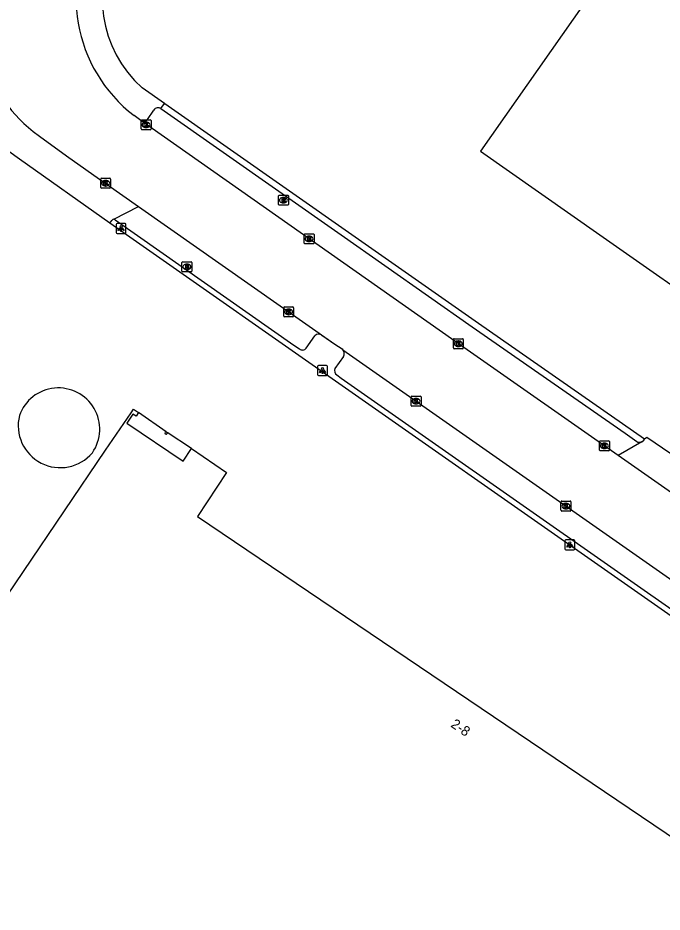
# Model space of a CAD drawing. Extents: x 155018 to 156648, y 383980 to 385733.
# Drawn here: x 155091.9 to 155156.9, y 384931.8 to 385021.9 of the extents above; entities that cross this region are included whole.
import ezdxf

# ---------------------------------------------------------------- set-up
doc = ezdxf.new("R2010")
doc.units = 0
for name, color, linetype in [('IMGEO_Brandkraan', 7, 'Continuous'), ('IMGEO_Kolk', 7, 'Continuous'), ('IMGEO_Lichtpunt', 7, 'Continuous'), ('IMGEO_Opslagtank', 7, 'Continuous'), ('IMGEO_Pand', 7, 'Continuous'), ('IMGEO_Pand_nummerreeks', 7, 'Continuous'), ('IMGEO_Pand_overbouw', 7, 'Continuous'), ('IMGEO_Rijbaan_lokaal_gesloten', 7, 'Continuous'), ('IMGEO_Rijbaan_lokaal_open', 7, 'Continuous'), ('IMGEO_Rioolput', 7, 'Continuous'), ('IMGEO_Voetpad_open', 7, 'Continuous')]:
    doc.layers.add(name, color=color, linetype=linetype)

msp = doc.modelspace()

# ---------------------------------------------------------------- linework, layer by layer
at = {"layer": 'IMGEO_Brandkraan'}
for p, q in [((155108.472, 384996.358), (155108.472, 384997.21)), ((155108.547, 384997.284), (155109.399, 384997.284)), ((155108.96, 384997.064), (155108.985, 384997.064)), ((155109.473, 384997.21), (155109.473, 384996.358)), ((155109.399, 384996.284), (155108.547, 384996.284)), ((155108.983, 384996.504), (155108.958, 384996.504))]:
    msp.add_line(p, q, dxfattribs=at)
for points in [[(155108.472, 384996.358), (155108.472, 384997.21)], [(155108.547, 384997.284), (155109.399, 384997.284)], [(155109.473, 384997.21), (155109.473, 384996.358)], [(155109.399, 384996.284), (155108.547, 384996.284)], [(155108.82, 384996.984), (155108.82, 384996.584), (155109.033, 384996.584)], [(155109.051, 384996.984), (155108.82, 384996.984)], [(155108.999, 384996.903), (155108.945, 384996.903), (155108.945, 384996.827)], [(155108.945, 384996.827), (155108.998, 384996.827)], [(155109.007, 384996.751), (155108.945, 384996.751), (155108.945, 384996.67)], [(155108.945, 384996.67), (155109.007, 384996.67)]]:
    msp.add_lwpolyline(points, dxfattribs=at)
for centre, radius, start, end in [((155108.549, 384997.208), 0.0765, 91.55205, 178.44795), ((155108.549, 384997.208), 0.0765, 91.55205, 178.44795), ((155109.397, 384997.208), 0.0765, 1.55205, 88.44795), ((155109.397, 384997.208), 0.0765, 1.55205, 88.44795), ((155108.549, 384996.36), 0.0765, 181.55205, 268.44795), ((155108.549, 384996.36), 0.0765, 181.55205, 268.44795), ((155109, 384996.865), 0.0379, 267.82845, 90.93552), ((155109.008, 384996.71), 0.0404, 269.87594, 90.50774), ((155109.039, 384996.835), 0.251, 268.66757, 293.53466), ((155109.055, 384996.839), 0.145, 59.4692, 91.53667), ((155109.08, 384996.886), 0.0922, 285.51372, 58.15012), ((155109.085, 384996.694), 0.105, 301.31148, 78.98903), ((155109.397, 384996.36), 0.0765, 271.55205, 358.44795), ((155109.397, 384996.36), 0.0765, 271.55205, 358.44795)]:
    msp.add_arc(centre, radius, start, end, dxfattribs=at)
for centre, major_axis, ratio, start_param, end_param in [((155108.959, 384996.784), (-0.387, 0.002), 0.722429, 4.712389, 7.853982), ((155108.984, 384996.784), (-0.39, 0.002), 0.717154, 1.570796, 4.712389)]:
    msp.add_ellipse(centre, major_axis=major_axis, ratio=ratio, start_param=start_param, end_param=end_param, dxfattribs=at)
at = {"layer": 'IMGEO_Kolk'}
for p, q in [((155104.355, 385010.674), (155104.355, 385011.526)), ((155104.43, 385011.6), (155105.282, 385011.6)), ((155105.356, 385011.526), (155105.356, 385010.674)), ((155105.282, 385010.6), (155104.43, 385010.6)), ((155104.866, 385010.82), (155104.841, 385010.82)), ((155104.843, 385011.38), (155104.868, 385011.38)), ((155100.283, 385004.78), (155100.283, 385005.632)), ((155100.358, 385005.706), (155101.21, 385005.706)), ((155100.771, 385005.486), (155100.796, 385005.486)), ((155101.284, 385005.632), (155101.284, 385004.78)), ((155101.21, 385004.706), (155100.358, 385004.706)), ((155100.794, 385004.926), (155100.769, 385004.926)), ((155120.785, 384999.18), (155120.785, 385000.032)), ((155120.86, 385000.106), (155121.712, 385000.106)), ((155121.273, 384999.886), (155121.298, 384999.886)), ((155121.786, 385000.032), (155121.786, 384999.18)), ((155121.712, 384999.106), (155120.86, 384999.106)), ((155121.296, 384999.326), (155121.271, 384999.326)), ((155118.723, 384991.815), (155118.723, 384992.667)), ((155118.798, 384992.741), (155119.65, 384992.741)), ((155119.211, 384992.521), (155119.236, 384992.521)), ((155119.724, 384992.667), (155119.724, 384991.815)), ((155119.65, 384991.741), (155118.798, 384991.741)), ((155119.234, 384991.961), (155119.209, 384991.961)), ((155135.823, 384988.611), (155135.823, 384989.463)), ((155135.898, 384989.537), (155136.75, 384989.537)), ((155136.311, 384989.317), (155136.336, 384989.317)), ((155136.824, 384989.463), (155136.824, 384988.611)), ((155136.75, 384988.537), (155135.898, 384988.537)), ((155136.334, 384988.757), (155136.309, 384988.757)), ((155131.563, 384982.826), (155131.563, 384983.678)), ((155131.638, 384983.752), (155132.49, 384983.752)), ((155132.051, 384983.532), (155132.076, 384983.532)), ((155132.564, 384983.678), (155132.564, 384982.826)), ((155132.49, 384982.752), (155131.638, 384982.752)), ((155132.074, 384982.972), (155132.049, 384982.972)), ((155150.546, 384978.324), (155150.546, 384979.176)), ((155150.621, 384979.25), (155151.473, 384979.25)), ((155151.034, 384979.03), (155151.059, 384979.03)), ((155151.547, 384979.176), (155151.547, 384978.324)), ((155151.473, 384978.25), (155150.621, 384978.25)), ((155151.057, 384978.47), (155151.032, 384978.47)), ((155146.67, 384972.25), (155146.67, 384973.102)), ((155146.745, 384973.176), (155147.597, 384973.176)), ((155147.158, 384972.956), (155147.183, 384972.956)), ((155147.671, 384973.102), (155147.671, 384972.25)), ((155147.597, 384972.176), (155146.745, 384972.176)), ((155147.181, 384972.396), (155147.156, 384972.396))]:
    msp.add_line(p, q, dxfattribs=at)
for points in [[(155104.355, 385010.674), (155104.355, 385011.526)], [(155104.43, 385011.6), (155105.282, 385011.6)], [(155105.356, 385011.526), (155105.356, 385010.674)], [(155105.282, 385010.6), (155104.43, 385010.6)], [(155104.676, 385011.3), (155104.799, 385011.3), (155104.799, 385011.149), (155104.929, 385011.3), (155105.093, 385011.3), (155104.947, 385011.149), (155105.1, 385010.9), (155104.948, 385010.9), (155104.863, 385011.064), (155104.799, 385010.997), (155104.799, 385010.9), (155104.676, 385010.9), (155104.676, 385011.3)], [(155100.283, 385004.78), (155100.283, 385005.632)], [(155100.358, 385005.706), (155101.21, 385005.706)], [(155100.604, 385005.406), (155100.727, 385005.406), (155100.727, 385005.255), (155100.857, 385005.406), (155101.021, 385005.406), (155100.875, 385005.255), (155101.028, 385005.006), (155100.876, 385005.006), (155100.791, 385005.17), (155100.727, 385005.103), (155100.727, 385005.006), (155100.604, 385005.006), (155100.604, 385005.406)], [(155101.284, 385005.632), (155101.284, 385004.78)], [(155101.21, 385004.706), (155100.358, 385004.706)], [(155120.785, 384999.18), (155120.785, 385000.032)], [(155120.86, 385000.106), (155121.712, 385000.106)], [(155121.106, 384999.806), (155121.229, 384999.806), (155121.229, 384999.655), (155121.359, 384999.806), (155121.523, 384999.806), (155121.377, 384999.655), (155121.53, 384999.406), (155121.378, 384999.406), (155121.293, 384999.57), (155121.229, 384999.503), (155121.229, 384999.406), (155121.106, 384999.406), (155121.106, 384999.806)], [(155121.786, 385000.032), (155121.786, 384999.18)], [(155121.712, 384999.106), (155120.86, 384999.106)], [(155118.723, 384991.815), (155118.723, 384992.667)], [(155118.798, 384992.741), (155119.65, 384992.741)], [(155119.724, 384992.667), (155119.724, 384991.815)], [(155119.65, 384991.741), (155118.798, 384991.741)], [(155119.044, 384992.441), (155119.167, 384992.441), (155119.167, 384992.29), (155119.297, 384992.441), (155119.461, 384992.441), (155119.315, 384992.29), (155119.468, 384992.041), (155119.316, 384992.041), (155119.231, 384992.205), (155119.167, 384992.138), (155119.167, 384992.041), (155119.044, 384992.041), (155119.044, 384992.441)], [(155135.823, 384988.611), (155135.823, 384989.463)], [(155135.898, 384989.537), (155136.75, 384989.537)], [(155136.144, 384989.237), (155136.267, 384989.237), (155136.267, 384989.086), (155136.397, 384989.237), (155136.561, 384989.237), (155136.415, 384989.086), (155136.568, 384988.837), (155136.416, 384988.837), (155136.331, 384989.001), (155136.267, 384988.934), (155136.267, 384988.837), (155136.144, 384988.837), (155136.144, 384989.237)], [(155136.824, 384989.463), (155136.824, 384988.611)], [(155136.75, 384988.537), (155135.898, 384988.537)], [(155131.563, 384982.826), (155131.563, 384983.678)], [(155131.638, 384983.752), (155132.49, 384983.752)], [(155132.564, 384983.678), (155132.564, 384982.826)], [(155132.49, 384982.752), (155131.638, 384982.752)], [(155131.884, 384983.452), (155132.007, 384983.452), (155132.007, 384983.301), (155132.137, 384983.452), (155132.301, 384983.452), (155132.155, 384983.301), (155132.308, 384983.052), (155132.156, 384983.052), (155132.071, 384983.216), (155132.007, 384983.149), (155132.007, 384983.052), (155131.884, 384983.052), (155131.884, 384983.452)], [(155150.546, 384978.324), (155150.546, 384979.176)], [(155150.621, 384979.25), (155151.473, 384979.25)], [(155151.547, 384979.176), (155151.547, 384978.324)], [(155151.473, 384978.25), (155150.621, 384978.25)], [(155150.867, 384978.95), (155150.99, 384978.95), (155150.99, 384978.799), (155151.12, 384978.95), (155151.284, 384978.95), (155151.138, 384978.799), (155151.291, 384978.55), (155151.139, 384978.55), (155151.054, 384978.714), (155150.99, 384978.647), (155150.99, 384978.55), (155150.867, 384978.55), (155150.867, 384978.95)], [(155146.67, 384972.25), (155146.67, 384973.102)], [(155146.745, 384973.176), (155147.597, 384973.176)], [(155146.991, 384972.876), (155147.114, 384972.876), (155147.114, 384972.725), (155147.244, 384972.876), (155147.408, 384972.876), (155147.262, 384972.725), (155147.415, 384972.476), (155147.263, 384972.476), (155147.178, 384972.64), (155147.114, 384972.573), (155147.114, 384972.476), (155146.991, 384972.476), (155146.991, 384972.876)], [(155147.671, 384973.102), (155147.671, 384972.25)], [(155147.597, 384972.176), (155146.745, 384972.176)]]:
    msp.add_lwpolyline(points, dxfattribs=at)
for centre, start, end in [((155104.432, 385011.524), 91.55205, 178.44795), ((155104.432, 385011.524), 91.55205, 178.44795), ((155105.28, 385011.524), 1.55205, 88.44795), ((155105.28, 385011.524), 1.55205, 88.44795), ((155104.432, 385010.676), 181.55205, 268.44795), ((155104.432, 385010.676), 181.55205, 268.44795), ((155105.28, 385010.676), 271.55205, 358.44795), ((155105.28, 385010.676), 271.55205, 358.44795), ((155100.36, 385005.63), 91.55205, 178.44795), ((155100.36, 385005.63), 91.55205, 178.44795), ((155101.208, 385005.63), 1.55205, 88.44795), ((155101.208, 385005.63), 1.55205, 88.44795), ((155100.36, 385004.782), 181.55205, 268.44795), ((155100.36, 385004.782), 181.55205, 268.44795), ((155101.208, 385004.782), 271.55205, 358.44795), ((155101.208, 385004.782), 271.55205, 358.44795), ((155120.862, 385000.03), 91.55205, 178.44795), ((155120.862, 385000.03), 91.55205, 178.44795), ((155121.71, 385000.03), 1.55205, 88.44795), ((155121.71, 385000.03), 1.55205, 88.44795), ((155120.862, 384999.182), 181.55205, 268.44795), ((155120.862, 384999.182), 181.55205, 268.44795), ((155121.71, 384999.182), 271.55205, 358.44795), ((155121.71, 384999.182), 271.55205, 358.44795), ((155118.8, 384992.665), 91.55205, 178.44795), ((155118.8, 384992.665), 91.55205, 178.44795), ((155119.648, 384992.665), 1.55205, 88.44795), ((155119.648, 384992.665), 1.55205, 88.44795), ((155118.8, 384991.817), 181.55205, 268.44795), ((155118.8, 384991.817), 181.55205, 268.44795), ((155119.648, 384991.817), 271.55205, 358.44795), ((155119.648, 384991.817), 271.55205, 358.44795), ((155135.9, 384989.461), 91.55205, 178.44795), ((155135.9, 384989.461), 91.55205, 178.44795), ((155136.748, 384989.461), 1.55205, 88.44795), ((155136.748, 384989.461), 1.55205, 88.44795), ((155135.9, 384988.613), 181.55205, 268.44795), ((155135.9, 384988.613), 181.55205, 268.44795), ((155136.748, 384988.613), 271.55205, 358.44795), ((155136.748, 384988.613), 271.55205, 358.44795), ((155131.64, 384983.676), 91.55205, 178.44795), ((155131.64, 384983.676), 91.55205, 178.44795), ((155132.488, 384983.676), 1.55205, 88.44795), ((155132.488, 384983.676), 1.55205, 88.44795), ((155131.64, 384982.828), 181.55205, 268.44795), ((155131.64, 384982.828), 181.55205, 268.44795), ((155132.488, 384982.828), 271.55205, 358.44795), ((155132.488, 384982.828), 271.55205, 358.44795), ((155150.623, 384979.174), 91.55205, 178.44795), ((155150.623, 384979.174), 91.55205, 178.44795), ((155151.471, 384979.174), 1.55205, 88.44795), ((155151.471, 384979.174), 1.55205, 88.44795), ((155150.623, 384978.326), 181.55205, 268.44795), ((155150.623, 384978.326), 181.55205, 268.44795), ((155151.471, 384978.326), 271.55205, 358.44795), ((155151.471, 384978.326), 271.55205, 358.44795), ((155146.747, 384973.1), 91.55205, 178.44795), ((155146.747, 384973.1), 91.55205, 178.44795), ((155147.595, 384973.1), 1.55205, 88.44795), ((155147.595, 384973.1), 1.55205, 88.44795), ((155146.747, 384972.252), 181.55205, 268.44795), ((155146.747, 384972.252), 181.55205, 268.44795), ((155147.595, 384972.252), 271.55205, 358.44795), ((155147.595, 384972.252), 271.55205, 358.44795)]:
    msp.add_arc(centre, 0.0765, start, end, dxfattribs=at)
for centre, major_axis, ratio, start_param, end_param in [((155104.842, 385011.1), (-0.387, 0.002), 0.722429, 4.712389, 7.853982), ((155104.867, 385011.1), (-0.39, 0.002), 0.717154, 1.570796, 4.712389), ((155100.77, 385005.206), (-0.387, 0.002), 0.722429, 4.712389, 7.853982), ((155100.795, 385005.206), (-0.39, 0.002), 0.717154, 1.570796, 4.712389), ((155121.272, 384999.606), (-0.387, 0.002), 0.722429, 4.712389, 7.853982), ((155121.297, 384999.606), (-0.39, 0.002), 0.717154, 1.570796, 4.712389), ((155119.21, 384992.241), (-0.387, 0.002), 0.722429, 4.712389, 7.853982), ((155119.235, 384992.241), (-0.39, 0.002), 0.717154, 1.570796, 4.712389), ((155136.31, 384989.037), (-0.387, 0.002), 0.722429, 4.712389, 7.853982), ((155136.335, 384989.037), (-0.39, 0.002), 0.717154, 1.570796, 4.712389), ((155132.05, 384983.252), (-0.387, 0.002), 0.722429, 4.712389, 7.853982), ((155132.075, 384983.252), (-0.39, 0.002), 0.717154, 1.570796, 4.712389), ((155151.033, 384978.75), (-0.387, 0.002), 0.722429, 4.712389, 7.853982), ((155151.058, 384978.75), (-0.39, 0.002), 0.717154, 1.570796, 4.712389), ((155147.157, 384972.676), (-0.387, 0.002), 0.722429, 4.712389, 7.853982), ((155147.182, 384972.676), (-0.39, 0.002), 0.717154, 1.570796, 4.712389)]:
    msp.add_ellipse(centre, major_axis=major_axis, ratio=ratio, start_param=start_param, end_param=end_param, dxfattribs=at)
at = {"layer": 'IMGEO_Lichtpunt'}
for p, q in [((155101.831, 385001.059), (155101.831, 385000.252)), ((155101.831, 385001.059), (155101.831, 385000.252)), ((155102.733, 385001.154), (155101.925, 385001.154)), ((155102.733, 385001.154), (155101.925, 385001.154)), ((155102.827, 385000.252), (155102.827, 385001.059)), ((155102.827, 385000.252), (155102.827, 385001.059)), ((155101.925, 385000.158), (155102.733, 385000.158)), ((155101.925, 385000.158), (155102.733, 385000.158)), ((155122.133, 384986.732), (155122.133, 384985.925)), ((155122.133, 384986.732), (155122.133, 384985.925)), ((155123.035, 384986.827), (155122.227, 384986.827)), ((155123.035, 384986.827), (155122.227, 384986.827)), ((155123.129, 384985.925), (155123.129, 384986.732)), ((155123.129, 384985.925), (155123.129, 384986.732)), ((155122.227, 384985.831), (155123.035, 384985.831)), ((155122.227, 384985.831), (155123.035, 384985.831)), ((155147.066, 384969.176), (155147.066, 384968.369)), ((155147.066, 384969.176), (155147.066, 384968.369)), ((155147.968, 384969.271), (155147.16, 384969.271)), ((155147.968, 384969.271), (155147.16, 384969.271)), ((155148.062, 384968.369), (155148.062, 384969.176)), ((155148.062, 384968.369), (155148.062, 384969.176)), ((155147.16, 384968.275), (155147.968, 384968.275)), ((155147.16, 384968.275), (155147.968, 384968.275))]:
    msp.add_line(p, q, dxfattribs=at)
for points in [[(155102.205, 385000.723), (155102.244, 385000.695), (155102.056, 385000.433), (155102.018, 385000.46), (155102.205, 385000.723)], [(155102.307, 385000.675), (155102.354, 385000.675), (155102.354, 385000.353), (155102.307, 385000.353), (155102.307, 385000.675)], [(155102.417, 385000.695), (155102.455, 385000.722), (155102.642, 385000.46), (155102.603, 385000.432), (155102.417, 385000.695)], [(155122.507, 384986.396), (155122.546, 384986.368), (155122.358, 384986.106), (155122.32, 384986.133), (155122.507, 384986.396)], [(155122.609, 384986.348), (155122.656, 384986.348), (155122.656, 384986.026), (155122.609, 384986.026), (155122.609, 384986.348)], [(155122.719, 384986.368), (155122.757, 384986.395), (155122.944, 384986.133), (155122.905, 384986.105), (155122.719, 384986.368)], [(155147.44, 384968.84), (155147.479, 384968.812), (155147.291, 384968.55), (155147.253, 384968.577), (155147.44, 384968.84)], [(155147.542, 384968.792), (155147.589, 384968.792), (155147.589, 384968.47), (155147.542, 384968.47), (155147.542, 384968.792)], [(155147.652, 384968.812), (155147.69, 384968.839), (155147.877, 384968.577), (155147.838, 384968.549), (155147.652, 384968.812)]]:
    msp.add_lwpolyline(points, dxfattribs=at)
for centre in [(155102.33, 385000.857), (155122.632, 384986.53), (155147.565, 384968.974)]:
    msp.add_circle(centre, 0.0994, dxfattribs=at)
for centre, start, end in [((155101.925, 385001.059), 90, 180), ((155101.925, 385001.059), 90, 180), ((155102.733, 385001.059), 0, 90), ((155102.733, 385001.059), 0, 90), ((155101.925, 385000.252), 180, 270), ((155101.925, 385000.252), 180, 270), ((155102.733, 385000.252), 270, 0), ((155102.733, 385000.252), 270, 360), ((155122.227, 384986.732), 90, 180), ((155122.227, 384986.732), 90, 180), ((155123.035, 384986.732), 0, 90), ((155123.035, 384986.732), 0, 90), ((155122.227, 384985.925), 180, 270), ((155122.227, 384985.925), 180, 270), ((155123.035, 384985.925), 270, 0), ((155123.035, 384985.925), 270, 360), ((155147.16, 384969.176), 90, 180), ((155147.16, 384969.176), 90, 180), ((155147.968, 384969.176), 0, 90), ((155147.968, 384969.176), 0, 90), ((155147.16, 384968.369), 180, 270), ((155147.16, 384968.369), 180, 270), ((155147.968, 384968.369), 270, 0), ((155147.968, 384968.369), 270, 360)]:
    msp.add_arc(centre, 0.0946, start, end, dxfattribs=at)
at = {"layer": 'IMGEO_Opslagtank'}
for centre, radius, start, end in [((155096.016, 384980.413), 4.166, 325.26244, 160.46574), ((155096.208, 384980.786), 4.242, 166.08687, 319.64131)]:
    msp.add_arc(centre, radius, start, end, dxfattribs=at)
at = {"layer": 'IMGEO_Pand'}
for points in [[(155155.032, 385031.909), (155138.546, 385008.43), (155150.587, 385000), (155163.454, 384990.991), (155169.751, 385000), (155172.658, 385004.159), (155178.609, 385000), (155180.482, 384998.691), (155171.241, 384985.516), (155188.007, 384973.803), (155206.355, 385000), (155219.209, 385018.36), (155202.837, 385029.825)], [(155059.424, 384917.182), (155100.779, 384978.305), (155103.338, 384982.088), (155103.58, 384982.446), (155104.089, 384982.105), (155103.849, 384981.73), (155103.52, 384981.95), (155102.903, 384981.019), (155108.594, 384977.203), (155109.424, 384978.47), (155112.962, 384976.062), (155110.037, 384971.641), (155167.202, 384933.006), (155171.49, 384939.329), (155175.039, 384936.926), (155172.878, 384933.731), (155176.85, 384931.037)], [(155106.866, 384980.173), (155106.981, 384980.097)]]:
    msp.add_lwpolyline(points, dxfattribs=at)
for start, end in [(90, 270), (270.165, 22.91201)]:
    msp.add_arc((155106.866, 384980.048), 0.125, start, end, dxfattribs=at)
at = {"layer": 'IMGEO_Pand_overbouw'}
msp.add_lwpolyline([(155106.866, 384980.173), (155104.089, 384982.105), (155103.849, 384981.73), (155103.52, 384981.95), (155102.903, 384981.019), (155108.594, 384977.203), (155109.424, 384978.47), (155106.981, 384980.096)], dxfattribs=at)
for start, end in [(90, 270), (270.05818, 22.71468)]:
    msp.add_arc((155106.866, 384980.048), 0.125, start, end, dxfattribs=at)
at = {"layer": 'IMGEO_Rijbaan_lokaal_gesloten'}
for points in [[(155104.316, 385011.516), (155103.661, 385012.02)], [(155152.428, 384977.771), (155137.217, 384988.42), (155120.721, 385000), (155105.117, 385010.953), (155104.316, 385011.516)], [(155093.471, 385010.431), (155094.104, 385009.957), (155096.834, 385007.973), (155100.736, 385005.199), (155100.927, 385005.065), (155104.094, 385002.848)], [(155104.094, 385002.848), (155123.87, 384989.007)], [(155123.87, 384989.007), (155124.619, 384988.506), (155124.695, 384988.43)], [(155124.695, 384988.43), (155198.603, 384936.694)], [(155169.394, 384965.893), (155162.523, 384970.703), (155152.428, 384977.771)]]:
    msp.add_lwpolyline(points, dxfattribs=at)
for centre, radius, start, end in [((155112.677, 385023.842), 14.867, 146.77994, 232.67012), ((155102.748, 385022.138), 14.937, 194.2746, 231.60633)]:
    msp.add_arc(centre, radius, start, end, dxfattribs=at)
at = {"layer": 'IMGEO_Rijbaan_lokaal_open'}
for points in [[(155101.196, 385001.176), (155092.114, 385007.622), (155091.015, 385008.402), (155090.159, 385008.281), (155078.52, 385004.551)], [(155101.611, 385001.575), (155104.094, 385002.848)], [(155101.196, 385001.176), (155101.401, 385001.469)], [(155154.802, 384979.137), (155152.428, 384977.771)], [(155154.802, 384979.137), (155155.029, 384979.328), (155155.096, 384979.41)], [(155247.243, 384915.217), (155232.066, 384925.988), (155227.994, 384928.878), (155223.854, 384931.752), (155220.046, 384934.396), (155190.84, 384954.671), (155188.926, 384956.009), (155183.117, 384960.07), (155179.962, 384962.275), (155172.387, 384967.57), (155170.211, 384969.308), (155168.502, 384970.505), (155163.313, 384974.139), (155155.317, 384979.582), (155155.096, 384979.41)]]:
    msp.add_lwpolyline(points, dxfattribs=at)
msp.add_arc((155101.605, 385001.326), 0.249, 88.58696, 144.97885, dxfattribs=at)
at = {"layer": 'IMGEO_Rioolput'}
for p, q in [((155118.199, 385003.073), (155118.199, 385003.925)), ((155118.274, 385003.999), (155119.126, 385003.999)), ((155118.687, 385003.779), (155118.712, 385003.779)), ((155119.2, 385003.925), (155119.2, 385003.073)), ((155119.126, 385002.999), (155118.274, 385002.999)), ((155118.71, 385003.219), (155118.685, 385003.219))]:
    msp.add_line(p, q, dxfattribs=at)
for points in [[(155118.199, 385003.073), (155118.199, 385003.925)], [(155118.274, 385003.999), (155119.126, 385003.999)], [(155118.788, 385003.697), (155118.536, 385003.699), (155118.536, 385003.299)], [(155118.536, 385003.299), (155118.66, 385003.299), (155118.66, 385003.461), (155118.671, 385003.461)], [(155118.714, 385003.618), (155118.66, 385003.618), (155118.66, 385003.537)], [(155118.66, 385003.537), (155118.712, 385003.537)], [(155118.718, 385003.432), (155118.789, 385003.299), (155118.929, 385003.299), (155118.864, 385003.425)], [(155119.2, 385003.925), (155119.2, 385003.073)], [(155119.126, 385002.999), (155118.274, 385002.999)]]:
    msp.add_lwpolyline(points, dxfattribs=at)
for centre, radius, start, end in [((155118.276, 385003.923), 0.0765, 91.55205, 178.44795), ((155118.276, 385003.923), 0.0765, 91.55205, 178.44795), ((155118.67, 385003.408), 0.0533, 26.02933, 88.69889), ((155118.696, 385003.726), 0.19, 274.7715, 282.96867), ((155118.72, 385003.522), 0.0964, 77.00612, 93.18647), ((155118.734, 385003.579), 0.0378, 276.66336, 79.67722), ((155118.787, 385003.587), 0.109, 350.36119, 89.41601), ((155118.785, 385003.587), 0.112, 277.58423, 350.98172), ((155118.769, 385003.372), 0.108, 29.51342, 73.79051), ((155119.124, 385003.923), 0.0765, 1.55205, 88.44795), ((155119.124, 385003.923), 0.0765, 1.55205, 88.44795), ((155118.276, 385003.075), 0.0765, 181.55205, 268.44795), ((155118.276, 385003.075), 0.0765, 181.55205, 268.44795), ((155119.124, 385003.075), 0.0765, 271.55205, 358.44795), ((155119.124, 385003.075), 0.0765, 271.55205, 358.44795)]:
    msp.add_arc(centre, radius, start, end, dxfattribs=at)
for centre, major_axis, ratio, start_param, end_param in [((155118.686, 385003.499), (-0.387, 0.002), 0.722429, 4.712389, 7.853982), ((155118.711, 385003.499), (-0.39, 0.002), 0.717154, 1.570796, 4.712389)]:
    msp.add_ellipse(centre, major_axis=major_axis, ratio=ratio, start_param=start_param, end_param=end_param, dxfattribs=at)
at = {"layer": 'IMGEO_Voetpad_open'}
for points in [[(155106.698, 385013.249), (155104.455, 385014.821)], [(155106.344, 385012.723), (155106.698, 385013.249)], [(155155.096, 384979.41), (155138.363, 384991.058), (155125.603, 385000), (155106.733, 385013.224), (155106.698, 385013.249)], [(155104.992, 385011.631), (155105.639, 385012.583)], [(155106.344, 385012.723), (155124.519, 385000), (155137.732, 384990.75), (155153.129, 384980.026), (155154.298, 384979.198)], [(155101.752, 385001.526), (155119.755, 384988.896), (155120.308, 384988.526)], [(155216.589, 384920.387), (155102.876, 385000), (155101.196, 385001.176)], [(155120.995, 384988.595), (155121.861, 384989.847)], [(155122.552, 384989.889), (155123.87, 384989.007)], [(155124.741, 384987.761), (155123.882, 384986.54)], [(155124.083, 384985.887), (155124.518, 384985.577), (155196.547, 384935.173)]]:
    msp.add_lwpolyline(points, dxfattribs=at)
for centre, radius, start, end in [((155112.471, 385023.791), 12.03, 148.56421, 228.21344), ((155106.061, 385012.301), 0.508, 56.20767, 146.25586), ((155104.589, 385011.958), 0.519, 238.30455, 321.00472), ((155101.601, 385001.318), 0.257, 53.96785, 87.70566), ((155122.23, 384989.482), 0.519, 51.65061, 135.30588), ((155120.622, 384988.856), 0.456, 226.47971, 324.99102), ((155124.254, 384988.064), 0.573, 328.14444, 39.72242), ((155124.377, 384986.335), 0.536, 157.49451, 236.72328), ((155154.603, 384979.604), 0.508, 233.11737, 293.08054)]:
    msp.add_arc(centre, radius, start, end, dxfattribs=at)

# ---------------------------------------------------------------- texts
at = {"layer": 'IMGEO_Pand_nummerreeks'}
msp.add_text('2-8', height=1, rotation=325.94718, dxfattribs=at).set_placement((155135.483, 384950.485))

doc.saveas('drawing.dxf')
